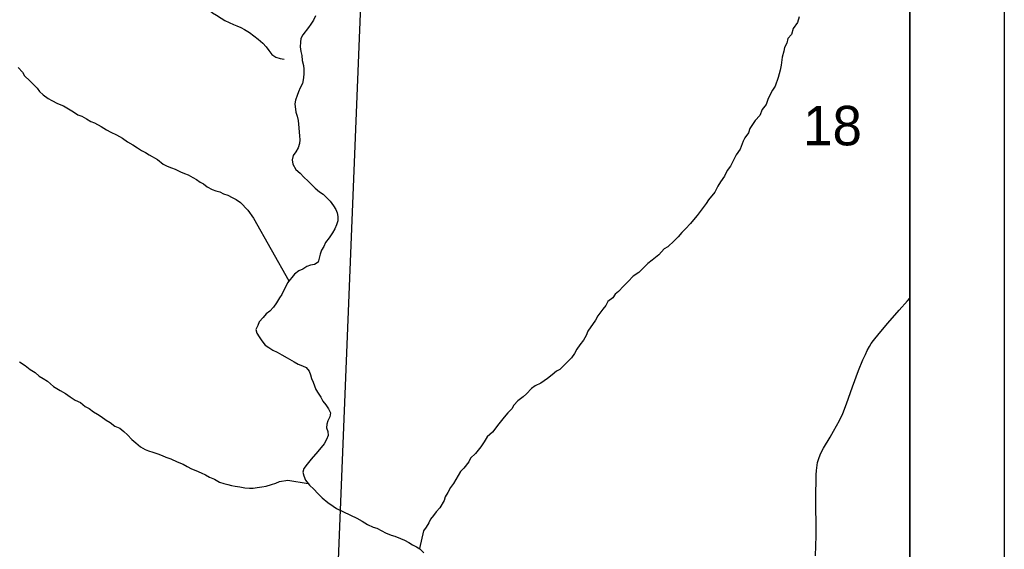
# Model space of a CAD drawing. Extents: x -7.9 to 76.1, y 0 to 22.
# Drawn here: x 7.957 to 9, y 17.321 to 17.882 of the extents above; entities that cross this region are included whole.
import ezdxf

# ---------------------------------------------------------------- set-up
doc = ezdxf.new("R2010")
doc.units = 0
for name, color, linetype in [('GM_X_County_Road', 7, 'Continuous'), ('GM_X_Minor_River', 7, 'Continuous'), ('GM_X_Section', 7, 'Continuous'), ('GM_X_Section_Text', 7, 'Continuous'), ('SC_Scratch1', 7, 'Continuous'), ('SH_Data', 7, 'Continuous')]:
    doc.layers.add(name, color=color, linetype=linetype)

msp = doc.modelspace()

# ---------------------------------------------------------------- linework, layer by layer
at = {"layer": 'GM_X_County_Road'}
msp.add_lwpolyline([(8.7999, 17.3142), (8.8006, 17.3355), (8.8005, 17.378), (8.8006, 17.3962), (8.8007, 17.4002), (8.8009, 17.4047), (8.8013, 17.4075), (8.8023, 17.4132), (8.8038, 17.4183), (8.8056, 17.4229), (8.8086, 17.4283), (8.8154, 17.44), (8.8192, 17.4463), (8.8256, 17.4577), (8.8289, 17.465), (8.833, 17.4752), (8.8393, 17.4934), (8.8457, 17.5104), (8.8501, 17.5217), (8.8528, 17.5276), (8.8549, 17.5318), (8.8572, 17.536), (8.8591, 17.539), (8.8613, 17.5422), (8.8673, 17.5497), (8.8766, 17.5606), (8.8888, 17.5746), (8.8973, 17.5843), (8.9, 17.5873)], dxfattribs=at)
at = {"layer": 'GM_X_Minor_River'}
for points in [[(8.1562, 17.8936), (8.1612, 17.8895), (8.1654, 17.8869), (8.1704, 17.8839), (8.1742, 17.8813), (8.1788, 17.8791), (8.1834, 17.8772), (8.1872, 17.8758), (8.1914, 17.8739), (8.1952, 17.8717), (8.2005, 17.8687), (8.2051, 17.865), (8.2097, 17.8616), (8.2147, 17.8575), (8.2182, 17.8534), (8.2209, 17.8497), (8.224, 17.8455), (8.2282, 17.8425), (8.2328, 17.8411), (8.2373, 17.8404)], [(8.2705, 17.8864), (8.2682, 17.8818), (8.2656, 17.8776), (8.263, 17.8738), (8.2571, 17.8661), (8.2549, 17.8623), (8.2545, 17.8585), (8.2542, 17.8535), (8.255, 17.8486), (8.2559, 17.8444), (8.2563, 17.8391), (8.2575, 17.8338), (8.258, 17.8297), (8.258, 17.8251), (8.2577, 17.8205), (8.2566, 17.8148), (8.2541, 17.8099), (8.2522, 17.8057), (8.2508, 17.8018), (8.2493, 17.7969), (8.2486, 17.7931), (8.2495, 17.7843), (8.2511, 17.7802), (8.2519, 17.7753), (8.2527, 17.7677), (8.2532, 17.7631), (8.2536, 17.7593), (8.2537, 17.7548), (8.2534, 17.751), (8.2519, 17.7464), (8.2497, 17.7422), (8.2467, 17.7384), (8.2456, 17.7338), (8.2464, 17.7292), (8.2496, 17.7236), (8.2542, 17.7195), (8.258, 17.7153), (8.2626, 17.7112), (8.2661, 17.7075), (8.2699, 17.7037), (8.2745, 17.7), (8.2784, 17.6974), (8.286, 17.6899), (8.2895, 17.685), (8.2919, 17.6812), (8.2934, 17.6775), (8.2942, 17.6737), (8.2939, 17.6691), (8.2928, 17.6649), (8.291, 17.6607), (8.2884, 17.6565), (8.2847, 17.6511), (8.281, 17.6461), (8.2791, 17.6419), (8.2769, 17.6381), (8.2754, 17.6339), (8.2744, 17.6297), (8.2733, 17.6252), (8.2695, 17.6228), (8.265, 17.622), (8.2612, 17.6208), (8.2571, 17.6181), (8.2529, 17.6161), (8.2481, 17.6126), (8.2406, 17.6034), (8.2347, 17.5912), (8.2321, 17.5874), (8.2291, 17.5824), (8.2258, 17.5778), (8.222, 17.5735), (8.2183, 17.5705), (8.2149, 17.5666), (8.2108, 17.562), (8.2094, 17.5582), (8.2071, 17.554), (8.2083, 17.5502), (8.2107, 17.5464), (8.2134, 17.5419), (8.2172, 17.5374), (8.2211, 17.5348), (8.2253, 17.5322), (8.2299, 17.53), (8.2348, 17.527), (8.2402, 17.524), (8.2478, 17.5196), (8.252, 17.5174)], [(8.7827, 17.8852), (8.7809, 17.8791), (8.7765, 17.873), (8.7747, 17.8665), (8.7706, 17.8623), (8.7695, 17.8573), (8.7673, 17.8527), (8.7666, 17.8489), (8.7648, 17.8424), (8.7637, 17.8341), (8.7627, 17.8287), (8.7605, 17.8211), (8.7572, 17.8119), (8.7546, 17.8077), (8.752, 17.8031), (8.7494, 17.7978), (8.7476, 17.7924), (8.7435, 17.7871), (8.741, 17.7809), (8.7361, 17.7756), (8.7331, 17.7713), (8.7305, 17.7671), (8.7291, 17.7622), (8.725, 17.7572), (8.7235, 17.7534), (8.7202, 17.745), (8.7161, 17.7392), (8.7143, 17.7354), (8.7098, 17.727), (8.7065, 17.7224), (8.7035, 17.7166), (8.6995, 17.7105), (8.6965, 17.7059), (8.6932, 17.6994), (8.6868, 17.6913), (8.6842, 17.6875), (8.6745, 17.6748), (8.6708, 17.6702), (8.6675, 17.6664), (8.6622, 17.6606), (8.6585, 17.6567), (8.6544, 17.6521), (8.6503, 17.6479), (8.6435, 17.6417), (8.6398, 17.6394), (8.6342, 17.6332), (8.627, 17.6274), (8.6225, 17.6239), (8.618, 17.6197), (8.6128, 17.6143), (8.6068, 17.6104), (8.6016, 17.6047), (8.5967, 17.6), (8.5915, 17.5943), (8.5877, 17.5916), (8.5855, 17.5877), (8.5802, 17.5835), (8.578, 17.5796), (8.5747, 17.5754), (8.5695, 17.5685), (8.5669, 17.5639), (8.5587, 17.5524), (8.5572, 17.5478), (8.5543, 17.5428), (8.5505, 17.5379), (8.5472, 17.5333), (8.5446, 17.5287), (8.5416, 17.5241), (8.5379, 17.5206), (8.5341, 17.5164), (8.5293, 17.5117), (8.5255, 17.5098), (8.521, 17.5059), (8.5161, 17.5021), (8.509, 17.497), (8.503, 17.4943), (8.4992, 17.4916), (8.494, 17.4858), (8.4902, 17.4827), (8.4846, 17.4784), (8.4805, 17.4738), (8.4783, 17.47), (8.4742, 17.4658), (8.4704, 17.4612), (8.4645, 17.4542), (8.4578, 17.4454), (8.4522, 17.4404), (8.4492, 17.435), (8.4455, 17.4297), (8.4399, 17.4227), (8.4346, 17.4177), (8.4328, 17.4139), (8.4276, 17.407), (8.4238, 17.4035), (8.4216, 17.3993)], [(7.9553, 17.8315), (7.96, 17.8267), (7.9623, 17.8229), (7.9677, 17.8173), (7.9715, 17.8135), (7.9757, 17.8098), (7.9781, 17.806), (7.9819, 17.8027), (7.9873, 17.7989), (7.9911, 17.7967), (7.9972, 17.7934), (8.0033, 17.7908), (8.0086, 17.7878), (8.014, 17.7845), (8.0186, 17.7815), (8.0228, 17.7801), (8.0278, 17.7771), (8.0323, 17.7745), (8.0362, 17.773), (8.0434, 17.769), (8.0491, 17.7656), (8.0537, 17.763), (8.0595, 17.7604), (8.066, 17.7567), (8.0713, 17.753), (8.077, 17.7497), (8.082, 17.7463), (8.0862, 17.7437), (8.0904, 17.7415), (8.0943, 17.7389), (8.103, 17.7341), (8.1092, 17.7292), (8.1134, 17.727), (8.118, 17.7252), (8.1218, 17.7237), (8.1275, 17.7211), (8.1317, 17.7193), (8.1355, 17.7178), (8.1405, 17.7152), (8.1443, 17.713), (8.1481, 17.71), (8.1519, 17.7082), (8.1558, 17.7052), (8.1611, 17.7022), (8.1649, 17.7008), (8.1691, 17.6997), (8.1729, 17.6978), (8.1775, 17.6964), (8.1821, 17.6938), (8.1863, 17.6916), (8.1909, 17.6886), (8.1986, 17.6803), (8.2048, 17.6721), (8.2422, 17.6054)], [(7.957, 17.5197), (7.9627, 17.516), (7.9681, 17.5115), (7.9734, 17.5086), (7.9777, 17.5044), (7.9819, 17.5022), (7.9865, 17.4992), (7.993, 17.4936), (7.9999, 17.4892), (8.0056, 17.4862), (8.0106, 17.4825), (8.0159, 17.4791), (8.0213, 17.4766), (8.0263, 17.4724), (8.0308, 17.4702), (8.0351, 17.4669), (8.0393, 17.4643), (8.0435, 17.4617), (8.0488, 17.4579), (8.053, 17.4553), (8.058, 17.4516), (8.063, 17.4494), (8.0672, 17.446), (8.0714, 17.4423), (8.0757, 17.4374), (8.0799, 17.4341), (8.0849, 17.4296), (8.0898, 17.427), (8.0936, 17.4255), (8.0982, 17.4241), (8.1035, 17.4222), (8.1081, 17.4204), (8.1119, 17.4189), (8.1173, 17.4171), (8.1238, 17.4138), (8.1302, 17.4112), (8.1344, 17.409), (8.139, 17.4064), (8.1436, 17.4046), (8.1493, 17.402), (8.1539, 17.4001), (8.1581, 17.3975), (8.1635, 17.3953), (8.1688, 17.3924), (8.1734, 17.3909), (8.1776, 17.3898), (8.1814, 17.3888), (8.1852, 17.388), (8.1901, 17.3874), (8.1954, 17.3863), (8.2004, 17.386), (8.2045, 17.386), (8.2087, 17.3865), (8.2136, 17.3873), (8.2182, 17.3881), (8.2238, 17.3897), (8.2283, 17.3913), (8.2321, 17.3929), (8.2412, 17.3945), (8.2625, 17.391)], [(8.252, 17.5174), (8.2566, 17.5155), (8.2604, 17.5137), (8.2635, 17.5099), (8.2651, 17.5058), (8.2663, 17.502), (8.2678, 17.4982), (8.2706, 17.4903), (8.2733, 17.4865), (8.276, 17.4824), (8.2783, 17.4779), (8.2814, 17.4741), (8.2841, 17.47), (8.2861, 17.4658), (8.2854, 17.4616), (8.2836, 17.4574), (8.2825, 17.4536), (8.2821, 17.4498), (8.2833, 17.446), (8.2838, 17.4418), (8.2819, 17.4376), (8.2797, 17.433), (8.273, 17.4246), (8.2659, 17.4165), (8.2614, 17.4115), (8.2581, 17.4069), (8.257, 17.4027), (8.2582, 17.3989), (8.2598, 17.3944), (8.264, 17.3891), (8.2686, 17.3847), (8.2729, 17.3802), (8.2775, 17.3757), (8.2836, 17.3708), (8.289, 17.3667), (8.2928, 17.3645), (8.3142, 17.3541), (8.3199, 17.3508), (8.3253, 17.3475), (8.3314, 17.3445), (8.3352, 17.3434), (8.3405, 17.3408), (8.3447, 17.3386), (8.3505, 17.336), (8.3543, 17.3349), (8.3604, 17.3324), (8.3645, 17.3309), (8.3691, 17.3283), (8.3733, 17.3257), (8.3772, 17.3239), (8.381, 17.3216), (8.3852, 17.3175)], [(8.4216, 17.3993), (8.4164, 17.3909), (8.4135, 17.3867), (8.4105, 17.3813), (8.4079, 17.3767), (8.4068, 17.3729), (8.402, 17.3649), (8.3983, 17.361), (8.3953, 17.3568), (8.3923, 17.353), (8.3905, 17.3491), (8.3875, 17.3445), (8.3849, 17.3407), (8.3806, 17.3219)]]:
    msp.add_lwpolyline(points, dxfattribs=at)
at = {"layer": 'GM_X_Section'}
msp.add_lwpolyline([(7.3083, 18.1826), (8.3283, 18.1522), (8.2894, 17.1874), (7.2713, 17.2194)], close=True, dxfattribs=at)
at = {"layer": 'SC_Scratch1'}
msp.add_lwpolyline([(8.9, 17.1682), (8.9, 18.1379), (8.3283, 18.1522), (8.2894, 17.1874)], close=True, dxfattribs=at)
at = {"layer": 'SH_Data'}
for p, q in [((9, 21), (9, 14)), ((8.9, 20.9), (8.9, 14.1))]:
    msp.add_line(p, q, dxfattribs=at)

# ---------------------------------------------------------------- texts
at = {"layer": 'GM_X_Section_Text'}
msp.add_text('18', height=0.04186, rotation=0, dxfattribs=at).set_placement((8.7869, 17.7491))

doc.saveas('drawing.dxf')
